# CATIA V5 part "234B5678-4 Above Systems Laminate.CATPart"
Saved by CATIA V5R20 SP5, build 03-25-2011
Part number: 234B5678-4 Above Systems Laminate
Publications: "Offset.5"
Bounding box of the stored display mesh (mm): x 31565.137 to 31911.332, y -11350.28 to -11181.984, z 5298.065 to 5469.994
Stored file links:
  C:\Users\rem1927\Desktop\Current Explicit Composite Demo\234B5678-4 Above Systems Laminate.CATPart
  C:\Users\rem1927\Desktop\Current Explicit Composite Demo\234B5678-1 Composite Product.CATProduct
  C:\Users\rem1927\Desktop\Tess Product Demo R20\Catalog_TNA.CATMaterial
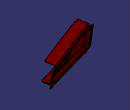
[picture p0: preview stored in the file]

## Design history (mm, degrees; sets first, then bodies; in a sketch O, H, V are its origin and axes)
AxisSystem1 "Rosette 3": origin (31647.2934, -11263.1074, 5379.7103), X (0.9552, 0.2927, -0.0445), Y (0, 0.1502, 0.9887), Z (0.2961, -0.9443, 0.1435)
CompParametersFeature1 "CATCoParametersFeatName": Value 0, Value 45, Value -45, Value 90, default 0
CompStacking1 "Stacking"
Set1
  Boundary1 "EOP Top Laminate": Boundary edge of DatumSurface1
  Offset1: Offset DatumSurface1, Length -1.5088
Set2 "Ply Group 3"
  Set3 "Sequence 300"
    Set4 "Ply 300"
      CLDGeom1 "Ply 300 Geometry"
  Set5 "Sequence 310"
    Set6 "Ply 310"
      CLDGeom2 "Ply 310 Geometry"
  Set7 "Sequence 320"
    Set8 "Ply 320"
      CLDGeom3 "Ply 320 Geometry"
Set9
  DatumPoint1 "Rose 4": linked copy from another document
  DatumCurve1 "Rose 3": linked copy from another document
  DatumCurve2 "Rose 2": linked copy from another document
  DatumSurface1 "Over Systems Layup Surface": linked copy from another document
  Plane1 "reference_plane": linked copy from another document
Body1 (main body)
Body2 "Ply 30"
  ThickSurface1: BotOffset 0, Surface DatumSurface1, TopOffset 1.0008
Body3 "Ply 31"
  ThickSurface2: BotOffset -1.0008, Surface DatumSurface1, TopOffset 1.2548
Body4 "Ply 32"
  ThickSurface3: BotOffset 0, Surface Offset1, TopOffset 0.254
